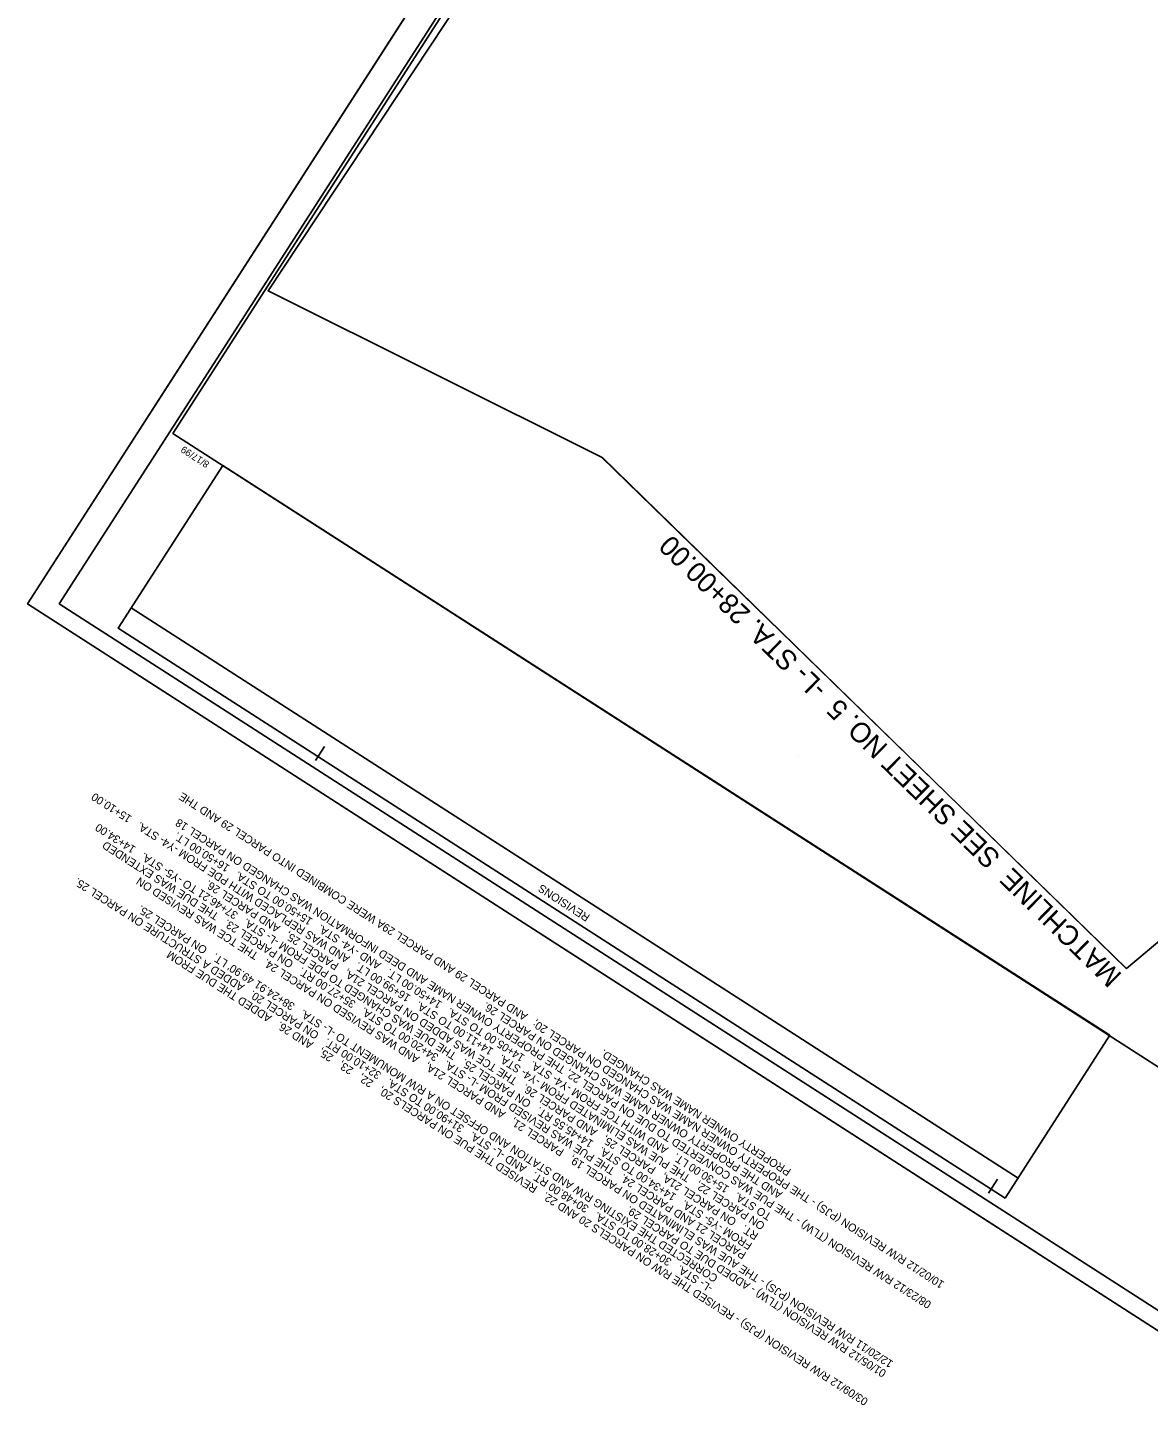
# Model space of a CAD drawing. Extents: x 1976127 to 1977958, y 779377 to 781490.
# Drawn here: x 1976127 to 1976967, y 779377 to 780410 of the extents above; entities that cross this region are included whole.
import ezdxf

# ---------------------------------------------------------------- set-up
doc = ezdxf.new("R2010")
doc.units = 0
for name, color, linetype in [('Matchline', 7, 'Continuous'), ('Matchline Text', 7, 'Continuous'), ('Sheet Block Revision CELL', 7, 'Continuous'), ('Sheet Clip Boundary CELL', 7, 'Continuous'), ('Sheet Cutting Line CELL', 7, 'Continuous'), ('Sheet Plan CELL', 7, 'Continuous'), ('Sheet Plan Layout CELL', 7, 'Continuous'), ('Sheet Plot Border Inside CELL', 7, 'Continuous'), ('Sheet Plot Border Outside CELL', 7, 'Continuous')]:
    doc.layers.add(name, color=color, linetype=linetype)

msp = doc.modelspace()

# ---------------------------------------------------------------- linework, layer by layer
at = {"layer": 'Matchline'}
msp.add_lwpolyline([(1976950.6, 779704.3), (1976753.8, 779896.5), (1976557.5, 780088.1)], dxfattribs=at)
at = {"layer": 'Sheet Block Revision CELL'}
msp.add_line((1976869.3, 779547.5), (1976204.3, 779975.2), dxfattribs=at)
msp.add_lwpolyline([(1976859.7, 779532.5), (1976194.5, 779959.9), (1976273, 780081.9), (1976938.1, 779654.6)], close=True, dxfattribs=at)
at = {"layer": 'Sheet Clip Boundary CELL'}
msp.add_lwpolyline([(1977101.1, 779831), (1977215.7, 780009.2), (1977355.5, 779919.3), (1977890.2, 780737.4), (1977684.7, 780893.8), (1977248.3, 781047.2), (1977166.5, 781076), (1977126.8, 781101.5), (1977076.7, 781133.9), (1977065, 781118.1), (1976959.9, 781185.7), (1976680, 780774.9), (1976779.9, 780758.8), (1976666.1, 780754.4), (1976646, 780725), (1976307, 780212.9), (1976557, 780088.2), (1976950.5, 779704.7)], close=True, dxfattribs=at)
at = {"layer": 'Sheet Cutting Line CELL'}
for p, q in [((1977037.3, 781394), (1976126.7, 779978)), ((1976126.7, 779978), (1977047.7, 779385.8))]:
    msp.add_line(p, q, dxfattribs=at)
at = {"layer": 'Sheet Plan CELL'}
for p, q in [((1976235.7, 780105.9), (1976235.7, 780105.9)), ((1976342.5, 779860.6), (1976349.2, 779871.2)), ((1976704.3, 779864), (1976704.3, 779864)), ((1976847.1, 779536.1), (1976853.9, 779546.6))]:
    msp.add_line(p, q, dxfattribs=at)
for points in [[(1977047, 781367.6), (1976235.7, 780105.9), (1977118.8, 779538), (1977930.2, 780799.6)], [(1977118.8, 779538), (1976235.7, 780105.9), (1976938.8, 781199.3), (1977065, 781118.1), (1977173.2, 781286.4), (1977930.2, 780799.6)]]:
    msp.add_lwpolyline(points, close=True, dxfattribs=at)
at = {"layer": 'Sheet Plan Layout CELL'}
msp.add_lwpolyline([(1976235.7, 780105.9), (1977118.8, 779538), (1977930.1, 780799.6), (1977224.9, 781253.1), (1977095.5, 781051.9), (1976917.6, 781166.3)], close=True, dxfattribs=at)
at = {"layer": 'Sheet Plot Border Inside CELL'}
msp.add_lwpolyline([(1977037.9, 779407.5), (1977939, 780808.8), (1977051.7, 781379.4), (1976150.5, 779978.2)], close=True, dxfattribs=at)
at = {"layer": 'Sheet Plot Border Outside CELL'}
msp.add_lwpolyline([(1977047.7, 779385.8), (1977958.3, 780801.7), (1977037.3, 781394), (1976126.7, 779978)], close=True, dxfattribs=at)

# ---------------------------------------------------------------- texts
at = {"layer": 'Matchline Text'}
msp.add_text('MATCHLINE  SEE SHEET NO. 5  -L- STA. 28+00.00', height=15, rotation=135.684, dxfattribs=at).set_placement((1976947.9, 779700.1))
at = {"layer": 'Sheet Block Revision CELL'}
for s, p in [('ON PARCEL 22,   THE PUE WAS ELIMINATED FROM -Y4- STA.   14+11.00 TO STA.   16+99.00 LT.   AND WAS REPLACED WITH PDE FROM -Y4- STA.   15+10.00', (1976680.1, 779513.2)), ('10/02/12 R/W REVISION (PJS) - THE PROPERTY OWNER NAME WAS CHANGED ON PARCEL 20;   AND PARCEL 29 AND PARCEL 29A WERE COMBINED INTO PARCEL 29 AND THE', (1976814.5, 779469.3)), ('FROM -Y5- STA.   14+34.00 TO STA.   14+45.55 RT.   ON PARCEL 25.   THE DUE WAS CHANGED TO PDE FROM -L- STA.   37+46.21 TO -Y5- STA.   14+34.00', (1976670.5, 779498.3)), ('08/23/12 R/W REVISION (TLW) - THE PUE WAS CONVERTED TO DUE ON PARCEL 22, THE PROPERTY OWNER NAME AND DEED INFORMATION WAS CHANGED ON PARCEL 18 ', (1976804.8, 779454.2)), ('PARCEL 21 AND PARCEL 24.   THE PUE WAS REVISED FROM -L- STA.   34+20.00 TO STA.   35+27.00 RT.   ON PARCEL 23.   THE DUE WAS EXTENDED', (1976666, 779491.3)), ('TO STA.   15+30.00 LT.   AND WITH TCE FROM -Y4- STA.   14+05.00 TO STA.   14+50.00 LT.   AND -Y4- STA.   15+50.00 TO STA.   16+50.00 LT.', (1976685, 779520.3)), ('-L- STA.   30+28.00 TO STA.   30+48.00 RT.   AND -L- STA.   31+90.00 TO STA.   32+10.00 RT.   ON PARCEL 20.   ADDED A STRUCTURE ON PARCEL 25.', (1976640.9, 779466.4)), ('12/20/11 R/W REVISION (PJS) - THE AUE WAS ELIMINATED ON PARCEL 19,   PARCEL 21,   AND PARCEL 21A,   AND WAS REVISED ON PARCEL 24.   THE TCE WAS REVISED ON', (1976776.2, 779409.8)), ('RT.   ON PARCEL 21A,   PARCEL 25,   AND PARCEL 26.   THE TCE WAS ADDED ON PARCEL 21A,   PARCEL 25,   AND PARCEL 26.', (1976675.2, 779505.7)), ('REVISIONS', (1976548.8, 779744.5)), ("CORRECTED THE EXISTING R/W AND STATION AND OFFSET ON A R/W MONUMENT TO -L- STA.   38+24.91 49.90' LT.   ON PARCEL 25.", (1976644.8, 779473.9)), ('03/09/12 R/W REVISION (PJS) - REVISED THE R/W ON PARCELS 20 AND 22.   REVISED THE PUE ON PARCELS 20,   22,   23,   25,   AND 26.   ADDED THE DUE FROM', (1976757.4, 779381.5)), ('AND THE PROPERTY OWNER NAME WAS CHANGED ON PARCEL 26.', (1976693.2, 779536.6)), ('PROPERTY OWNER NAME WAS CHANGED.', (1976699.6, 779553.7)), ('01/05/12 R/W REVISION (TLW) - ADDED DUE TO PARCEL 29.', (1976771, 779402.7))]:
    msp.add_text(s, height=6, rotation=147.255, dxfattribs=at).set_placement(p)
at = {"layer": 'Sheet Plan CELL'}
msp.add_text('8/17/99', height=5.25, rotation=147.255, dxfattribs=at).set_placement((1976263.5, 780084.1))

doc.saveas('drawing.dxf')
